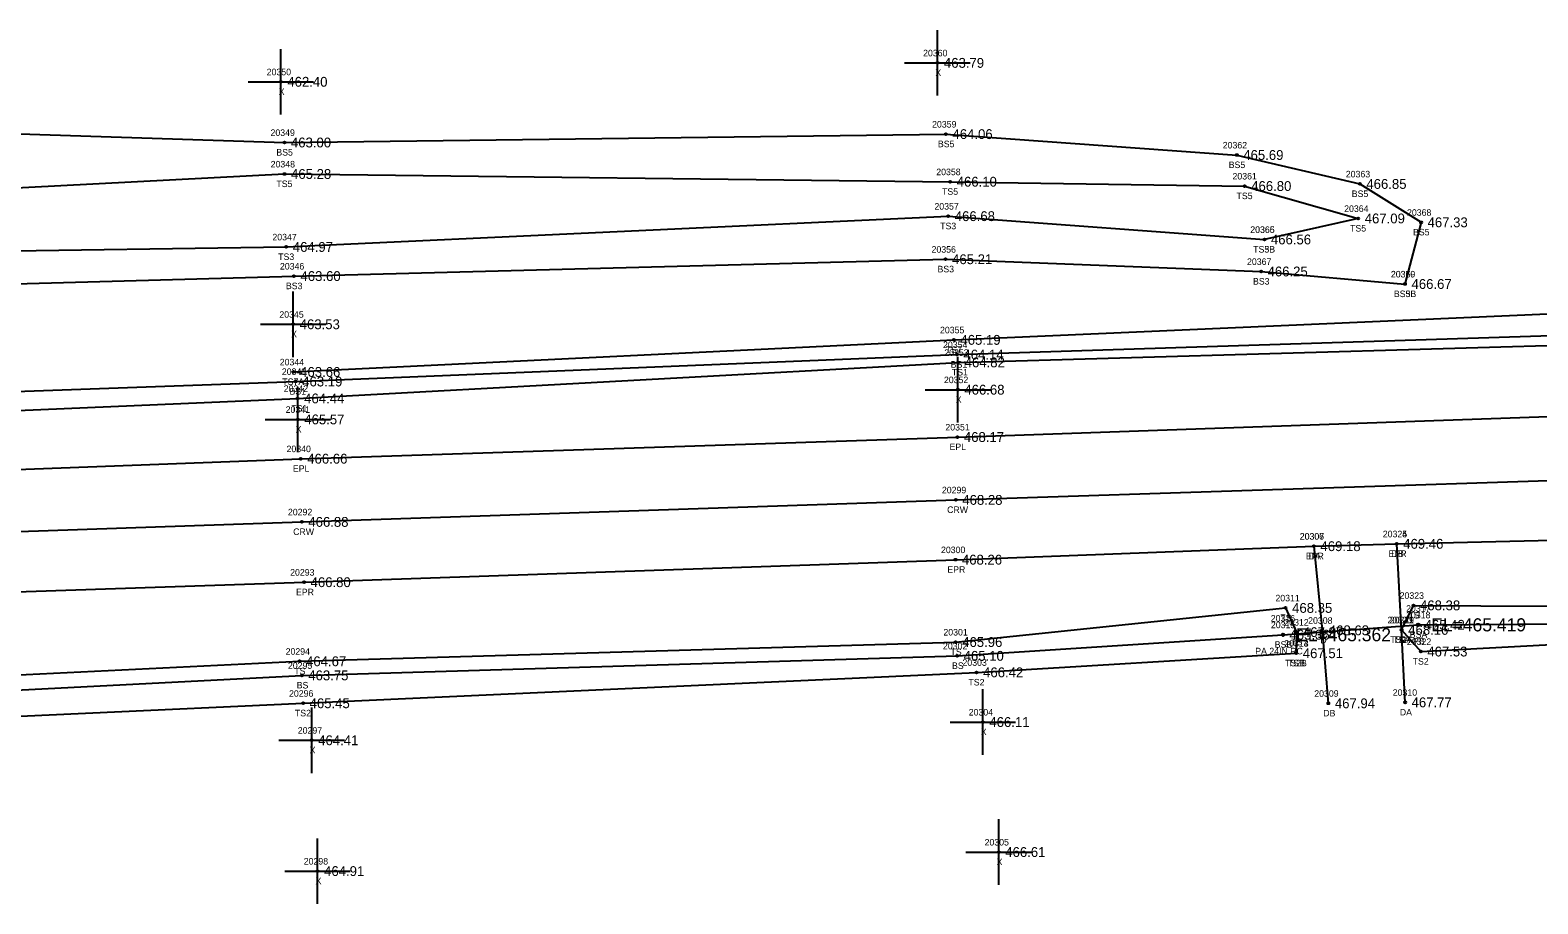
# Model space of a CAD drawing. Extents: x 1785066 to 1786589, y 770293 to 771312.
# Drawn here: x 1786037.5 to 1786267.8, y 770805.5 to 770939 of the extents above; entities that cross this region are included whole.
import ezdxf

# ---------------------------------------------------------------- set-up
doc = ezdxf.new("R2010")
doc.units = 0
for name, color, linetype in [('Default', 7, 'Continuous'), ('RD_DTM_BkLn1', 7, 'Continuous'), ('RD_DTM_BkLn2', 7, 'Continuous'), ('RD_DTM_BkLn_txCode', 7, 'Continuous'), ('RD_EX_DR_Pipe_txCode', 7, 'Continuous'), ('RD_EX_Driveway', 7, 'Continuous'), ('RD_EX_Driveway_txCode', 7, 'Continuous'), ('RD_EX_Misc', 7, 'Continuous'), ('RD_EX_Misc_txCode', 7, 'Continuous'), ('RD_EX_Road', 7, 'Continuous'), ('RD_EX_Road_txCode', 7, 'Continuous'), ('RD_EX_TX_Driveway_ELEV', 7, 'Continuous'), ('RD_EX_TX_Misc_ELEV', 7, 'Continuous'), ('RD_EX_TX_Road_ELEV', 7, 'Continuous'), ('RD_HC_Survey_ELEV', 7, 'Continuous'), ('RD_HC_Survey_txCode', 7, 'Continuous'), ('RD_SMD_Locator', 7, 'Continuous'), ('RD_TX_Pipe_ElevEX', 7, 'Continuous')]:
    doc.layers.add(name, color=color, linetype=linetype)

msp = doc.modelspace()

# ---------------------------------------------------------------- linework, layer by layer
at = {"layer": 'Default'}
msp.add_line((1786228.83, 770846.64), (1786249.47, 770848.15), dxfattribs=at)
at = {"layer": 'RD_DTM_BkLn1'}
msp.add_lwpolyline([(1785825, 770854.98), (1785879.1, 770857.22), (1785979.05, 770860.47), (1786078.95, 770863.87), (1786178.85, 770867.23), (1786278.74, 770870.52), (1786378.69, 770873.93), (1786478.55, 770877.83), (1786578.48, 770880.72)], dxfattribs=at)
at = {"layer": 'RD_DTM_BkLn2'}
for points in [[(1785924.35, 770938.04), (1785979.77, 770924.96), (1786076.29, 770921.81), (1786177.35, 770923.09), (1786221.77, 770919.9), (1786240.57, 770915.48), (1786249.92, 770909.62), (1786247.47, 770900.2)], [(1785908.96, 770920.93), (1785918.22, 770904.46), (1785926.35, 770898.09), (1785975.82, 770898.61), (1786077.75, 770901.41), (1786177.29, 770903.98), (1786225.48, 770902.11), (1786247.47, 770900.2)], [(1785930.03, 770918.87), (1785930.77, 770909.48), (1785938.68, 770905.47), (1785979.27, 770904.46), (1786076.58, 770905.86), (1786177.7, 770910.56), (1786225.99, 770907)], [(1785930.03, 770918.87), (1785938.67, 770915.93), (1785979.63, 770911.96), (1786076.31, 770917), (1786177.99, 770915.82), (1786222.98, 770915.16), (1786240.32, 770910.21), (1786225.99, 770907)], [(1786077.7, 770886.77), (1786178.56, 770891.67), (1786277.37, 770895.98), (1786358.4, 770903.56), (1786359.59, 770898.17), (1786358.22, 770894.11)], [(1785823.92, 770890.03), (1785878.49, 770883.8), (1785927.98, 770885.02), (1785976.75, 770881.71), (1786078.01, 770885.31), (1786179.02, 770889.42), (1786277.82, 770892.61), (1786356.85, 770898.28)], [(1785823.56, 770878.59), (1785827.04, 770881.87), (1785879.17, 770873.62), (1785928.77, 770880.68), (1785976.07, 770878.36), (1786078.31, 770882.72), (1786179.21, 770888.23), (1786278, 770891.06), (1786358.22, 770894.11)], [(1785823.92, 770890.03), (1785823.56, 770878.59), (1785822.86, 770870.38), (1785821.44, 770840.38), (1785828.62, 770840.78), (1785842.19, 770836.7), (1785879.25, 770839.01), (1785978.35, 770837.69), (1786078.6, 770842.58), (1786178.83, 770845.52), (1786229.23, 770850.73), (1786230.88, 770847.03), (1786230.86, 770843.81)], [(1786246.96, 770847.38), (1786248.77, 770851.12), (1786279.67, 770850.97), (1786379.11, 770855.94), (1786479.26, 770860.11), (1786579.22, 770863.72)], [(1786249.47, 770848.15), (1786280.2, 770848.37), (1786379.05, 770854.35), (1786479.51, 770858.4), (1786579.5, 770861.84)], [(1786246.96, 770847.38), (1786249.88, 770844.07), (1786279.41, 770845.63), (1786378.93, 770852.05), (1786480.11, 770854.27), (1786579.39, 770853.78)], [(1785827.67, 770829.52), (1785841.85, 770827.95), (1785844.56, 770828.57), (1785879.6, 770830.99), (1785978.6, 770835.28), (1786078.94, 770840.43), (1786179.05, 770843.41), (1786228.83, 770846.64)], [(1785823.45, 770822.61), (1785818.3, 770824.93), (1785815.32, 770825.6), (1785815.62, 770826.83), (1785818.45, 770825.65), (1785827.36, 770825.61), (1785879.44, 770828.14), (1785979.38, 770831.62), (1786079.14, 770836.17), (1786182.02, 770840.89), (1786230.86, 770843.81)]]:
    msp.add_lwpolyline(points, dxfattribs=at)
at = {"layer": 'RD_EX_Driveway'}
for points in [[(1786233.56, 770860.16), (1786234.84, 770847.31), (1786235.76, 770836.16)], [(1786247.48, 770836.31), (1786246.96, 770847.38), (1786246.2, 770860.52)]]:
    msp.add_lwpolyline(points, dxfattribs=at)
at = {"layer": 'RD_EX_Misc'}
for p, q in [((1786176.04, 770928.97), (1786176.04, 770938.97)), ((1786075.74, 770926.08), (1786075.74, 770936.08)), ((1786171.04, 770933.97), (1786181.04, 770933.97)), ((1786070.74, 770931.08), (1786080.74, 770931.08)), ((1786077.63, 770889.05), (1786077.63, 770899.05)), ((1786072.63, 770894.05), (1786082.63, 770894.05)), ((1786179.16, 770879.06), (1786179.16, 770889.06)), ((1786078.33, 770874.52), (1786078.33, 770884.52)), ((1786174.16, 770884.06), (1786184.16, 770884.06)), ((1786073.33, 770879.52), (1786083.33, 770879.52)), ((1786182.98, 770828.3), (1786182.98, 770838.3)), ((1786080.46, 770825.52), (1786080.46, 770835.52)), ((1786177.98, 770833.3), (1786187.98, 770833.3)), ((1786075.46, 770830.52), (1786085.46, 770830.52)), ((1786185.41, 770808.45), (1786185.41, 770818.45)), ((1786081.36, 770805.54), (1786081.36, 770815.54)), ((1786180.41, 770813.45), (1786190.41, 770813.45)), ((1786076.36, 770810.54), (1786086.36, 770810.54))]:
    msp.add_line(p, q, dxfattribs=at)
at = {"layer": 'RD_EX_Road'}
for points in [[(1785824.57, 770864.86), (1785879.1, 770866.73), (1785977.08, 770869.67), (1786078.78, 770873.52), (1786179.09, 770876.83), (1786278.08, 770880.28), (1786358.72, 770883.31), (1786381.38, 770883.94), (1786478.25, 770886.75), (1786578.04, 770889.63)], [(1785825.31, 770845.6), (1785879.29, 770848.18), (1785979.17, 770851.29), (1786079.29, 770854.66), (1786178.79, 770858.1), (1786233.56, 770860.16), (1786246.2, 770860.52), (1786278.61, 770861.3), (1786379.15, 770864.94), (1786479.01, 770868.57), (1786578.78, 770871.53)]]:
    msp.add_lwpolyline(points, dxfattribs=at)
at = {"layer": 'RD_SMD_Locator'}
for centre, radius in [((1786176.04, 770933.97), 0.15), ((1786075.74, 770931.08), 0.15), ((1786177.35, 770923.09), 0.15), ((1786076.29, 770921.81), 0.15), ((1786221.77, 770919.9), 0.15), ((1786076.31, 770917), 0.15), ((1786177.99, 770915.82), 0.15), ((1786222.98, 770915.16), 0.15), ((1786240.57, 770915.48), 0.15), ((1786177.7, 770910.56), 0.15), ((1786240.32, 770910.21), 0.15), ((1786249.92, 770909.62), 0.15), ((1786225.99, 770907), 0.15), ((1786225.99, 770907), 0.15), ((1786076.58, 770905.86), 0.15), ((1786177.29, 770903.98), 0.15), ((1786077.75, 770901.41), 0.15), ((1786225.48, 770902.11), 0.15), ((1786247.47, 770900.2), 0.15), ((1786247.47, 770900.2), 0.15), ((1786077.63, 770894.05), 0.15), ((1786178.56, 770891.67), 0.15), ((1786179.02, 770889.42), 0.15), ((1786077.7, 770886.77), 0.15), ((1786179.21, 770888.23), 0.15), ((1786078.01, 770885.31), 0.15), ((1786179.16, 770884.06), 0.15), ((1786078.31, 770882.72), 0.15), ((1786078.33, 770879.52), 0.15), ((1786179.09, 770876.83), 0.15), ((1786078.78, 770873.52), 0.15), ((1786178.85, 770867.23), 0.15), ((1786078.95, 770863.87), 0.15), ((1786233.56, 770860.16), 0.15), ((1786233.56, 770860.16), 0.15), ((1786246.2, 770860.52), 0.15), ((1786246.2, 770860.52), 0.15), ((1786178.79, 770858.1), 0.15), ((1786079.29, 770854.66), 0.15), ((1786229.23, 770850.73), 0.15), ((1786248.77, 770851.12), 0.15), ((1786230.88, 770847.03), 0.15), ((1786234.84, 770847.31), 0.15), ((1786246.96, 770847.38), 0.15), ((1786246.96, 770847.38), 0.15), ((1786246.96, 770847.38), 0.15), ((1786249.47, 770848.15), 0.2), ((1786249.47, 770848.15), 0.15), ((1786178.83, 770845.52), 0.15), ((1786228.83, 770846.64), 0.2), ((1786228.83, 770846.64), 0.15), ((1786078.6, 770842.58), 0.15), ((1786179.05, 770843.41), 0.15), ((1786230.86, 770843.81), 0.15), ((1786230.86, 770843.81), 0.15), ((1786249.88, 770844.07), 0.15), ((1786078.94, 770840.43), 0.15), ((1786182.02, 770840.89), 0.15), ((1786079.14, 770836.17), 0.15), ((1786235.76, 770836.16), 0.15), ((1786247.48, 770836.31), 0.15), ((1786182.98, 770833.3), 0.15), ((1786080.46, 770830.52), 0.15), ((1786185.41, 770813.45), 0.15), ((1786081.36, 770810.54), 0.15)]:
    msp.add_circle(centre, radius, dxfattribs=at)

# ---------------------------------------------------------------- texts
at = {"layer": 'RD_DTM_BkLn_txCode'}
for s, p in [('20349', (1786074.17, 770922.81)), ('20359', (1786175.23, 770924.09)), ('BS5', (1786075.06, 770919.81)), ('BS5', (1786176.12, 770921.09)), ('20362', (1786219.63, 770920.9)), ('20348', (1786074.19, 770918)), ('BS5', (1786220.54, 770917.9)), ('20358', (1786175.87, 770916.82)), ('20361', (1786221.12, 770916.16)), ('20363', (1786238.43, 770916.48)), ('TS5', (1786075.07, 770915)), ('TS5', (1786176.75, 770913.82)), ('TS5', (1786221.74, 770913.16)), ('BS5', (1786239.34, 770913.48)), ('20357', (1786175.59, 770911.56)), ('20364', (1786238.18, 770911.21)), ('20368', (1786247.78, 770910.62)), ('TS3', (1786176.46, 770908.56)), ('20347', (1786074.46, 770906.86)), ('20366', (1786223.83, 770908)), ('20365', (1786223.85, 770908)), ('TS5', (1786239.08, 770908.21)), ('BS5', (1786248.69, 770907.62)), ('TS3', (1786075.34, 770903.86)), ('20356', (1786175.15, 770904.98)), ('TS5B', (1786224.28, 770905)), ('TS3B', (1786224.28, 770905)), ('20346', (1786075.61, 770902.41)), ('BS3', (1786176.06, 770901.98)), ('20367', (1786223.34, 770903.11)), ('BS3', (1786076.52, 770899.41)), ('BS3', (1786224.25, 770900.11)), ('20370', (1786245.31, 770901.2)), ('20369', (1786245.32, 770901.2)), ('BS5B', (1786245.77, 770898.2)), ('BS3B', (1786245.77, 770898.2)), ('20355', (1786176.44, 770892.67)), ('20354', (1786176.9, 770890.42)), ('20344', (1786075.58, 770887.77)), ('20353', (1786177.09, 770889.23)), ('TS7', (1786177.31, 770889.67)), ('20343', (1786075.9, 770886.31)), ('BS1', (1786178.08, 770887.42)), ('TS1', (1786178.25, 770886.23)), ('TS7A', (1786075.97, 770884.77)), ('20342', (1786076.19, 770883.72)), ('BS1', (1786077.07, 770883.31)), ('TS1', (1786077.35, 770880.72)), ('20311', (1786227.68, 770851.73)), ('20323', (1786246.65, 770852.12)), ('TS', (1786228.43, 770848.73)), ('20320', (1786244.8, 770848.38)), ('20319', (1786245.12, 770848.38)), ('20318', (1786247.64, 770849.15)), ('TS', (1786247.98, 770849.12)), ('20301', (1786176.96, 770846.52)), ('20315', (1786226.99, 770847.64)), ('20312', (1786229.04, 770848.03)), ('BSA', (1786248.2, 770846.15)), ('20302', (1786176.89, 770844.41)), ('BSB', (1786227.57, 770844.64)), ('20313', (1786229.02, 770844.81)), ('20314', (1786229.02, 770844.81)), ('TS', (1786230.08, 770845.03)), ('TS2A', (1786245.22, 770845.38)), ('TSA', (1786245.67, 770845.38)), ('20322', (1786247.76, 770845.07)), ('20294', (1786076.48, 770843.58)), ('TS', (1786178.04, 770843.52)), ('20303', (1786179.87, 770841.89)), ('TS2B', (1786229.14, 770841.81)), ('TSB', (1786229.59, 770841.81)), ('TS2', (1786248.64, 770842.07)), ('20295', (1786076.83, 770841.43)), ('TS', (1786077.8, 770840.58)), ('BS', (1786178.27, 770841.41)), ('20296', (1786077, 770837.17)), ('BS', (1786078.17, 770838.43)), ('TS2', (1786180.78, 770838.89)), ('TS2', (1786077.9, 770834.17))]:
    msp.add_text(s, height=1, dxfattribs=at).set_placement(p)
at = {"layer": 'RD_EX_DR_Pipe_txCode'}
for s, p in [('20316', (1786226.97, 770848.64)), ('20317', (1786247.64, 770850.15)), ('PB', (1786248.69, 770845.15)), ('PA 24IN RC', (1786224.59, 770843.64))]:
    msp.add_text(s, height=1, dxfattribs=at).set_placement(p)
at = {"layer": 'RD_EX_Driveway_txCode'}
for s, p in [('20307', (1786231.41, 770861.16)), ('20324', (1786244.08, 770861.52)), ('DA', (1786232.77, 770858.16)), ('DB', (1786245.42, 770858.52)), ('20321', (1786245.12, 770848.38)), ('20308', (1786232.68, 770848.31)), ('D', (1786234.54, 770845.31)), ('D', (1786246.65, 770845.38)), ('20309', (1786233.61, 770837.16)), ('20310', (1786245.6, 770837.31)), ('DB', (1786234.98, 770834.16)), ('DA', (1786246.68, 770834.31))]:
    msp.add_text(s, height=1, dxfattribs=at).set_placement(p)
at = {"layer": 'RD_EX_Misc_txCode'}
for s, p in [('20360', (1786173.86, 770934.97)), ('20350', (1786073.59, 770932.08)), ('X', (1786175.73, 770931.97)), ('X', (1786075.43, 770929.08)), ('20345', (1786075.52, 770895.05)), ('X', (1786077.32, 770892.05)), ('20352', (1786177.04, 770885.06)), ('X', (1786178.84, 770882.06)), ('20341', (1786076.49, 770880.52)), ('X', (1786078.01, 770877.52)), ('20304', (1786180.83, 770834.3)), ('20297', (1786078.34, 770831.52)), ('X', (1786182.67, 770831.3)), ('X', (1786080.14, 770828.52)), ('20305', (1786183.25, 770814.45)), ('20298', (1786079.25, 770811.54)), ('X', (1786185.09, 770811.45)), ('X', (1786081.05, 770808.54))]:
    msp.add_text(s, height=1, dxfattribs=at).set_placement(p)
at = {"layer": 'RD_EX_Road_txCode'}
for s, p in [('20351', (1786177.26, 770877.83)), ('20340', (1786076.62, 770874.52)), ('EPL', (1786177.89, 770874.83)), ('EPL', (1786077.58, 770871.52)), ('20306', (1786231.38, 770861.16)), ('20325', (1786244.08, 770861.52)), ('20300', (1786176.59, 770859.1)), ('EPR', (1786232.33, 770858.16)), ('EPR', (1786244.97, 770858.52)), ('20293', (1786077.17, 770855.66)), ('EPR', (1786177.56, 770856.1)), ('EPR', (1786078.06, 770852.66))]:
    msp.add_text(s, height=1, dxfattribs=at).set_placement(p)
at = {"layer": 'RD_EX_TX_Driveway_ELEV'}
for s, p in [('469.18', (1786234.56, 770859.41)), ('469.46', (1786247.2, 770859.77)), ('468.63', (1786235.84, 770846.56)), ('468.16', (1786247.96, 770846.63)), ('467.94', (1786236.76, 770835.41)), ('467.77', (1786248.48, 770835.56))]:
    msp.add_text(s, height=1.5, dxfattribs=at).set_placement(p)
at = {"layer": 'RD_EX_TX_Misc_ELEV'}
for s, p in [('463.79', (1786177.04, 770933.22)), ('462.40', (1786076.74, 770930.33)), ('464.06', (1786178.35, 770922.34)), ('463.00', (1786077.29, 770921.06)), ('465.69', (1786222.77, 770919.15)), ('465.28', (1786077.31, 770916.25)), ('466.10', (1786178.99, 770915.07)), ('466.85', (1786241.57, 770914.73)), ('466.80', (1786223.98, 770914.41)), ('466.68', (1786178.7, 770909.81)), ('467.09', (1786241.32, 770909.46)), ('467.33', (1786250.92, 770908.87)), ('466.56', (1786226.99, 770906.25)), ('466.56', (1786226.99, 770906.25)), ('464.97', (1786077.58, 770905.11)), ('465.21', (1786178.29, 770903.23)), ('466.25', (1786226.48, 770901.36)), ('463.60', (1786078.75, 770900.66)), ('466.67', (1786248.47, 770899.45)), ('466.67', (1786248.47, 770899.45)), ('463.53', (1786078.63, 770893.3)), ('465.19', (1786179.56, 770890.92)), ('464.14', (1786180.02, 770888.67)), ('464.82', (1786180.21, 770887.48)), ('463.66', (1786078.7, 770886.02)), ('463.19', (1786079.01, 770884.56)), ('466.68', (1786180.16, 770883.31)), ('464.44', (1786079.31, 770881.97)), ('465.57', (1786079.33, 770878.77)), ('468.38', (1786249.77, 770850.37)), ('468.35', (1786230.23, 770849.98)), ('465.36', (1786229.83, 770845.89)), ('467.97', (1786231.88, 770846.28)), ('468.16', (1786247.96, 770846.63)), ('468.16', (1786247.96, 770846.63)), ('465.42', (1786250.47, 770847.4)), ('465.96', (1786179.83, 770844.77)), ('467.53', (1786250.88, 770843.32)), ('464.67', (1786079.6, 770841.83)), ('465.10', (1786180.05, 770842.66)), ('467.51', (1786231.86, 770843.06)), ('467.51', (1786231.86, 770843.06)), ('463.75', (1786079.94, 770839.68)), ('466.42', (1786183.02, 770840.14)), ('465.45', (1786080.14, 770835.42)), ('466.11', (1786183.98, 770832.55)), ('464.41', (1786081.46, 770829.77)), ('466.61', (1786186.41, 770812.7)), ('464.91', (1786082.36, 770809.79))]:
    msp.add_text(s, height=1.5, dxfattribs=at).set_placement(p)
at = {"layer": 'RD_EX_TX_Road_ELEV'}
for s, p in [('468.17', (1786180.09, 770876.08)), ('466.66', (1786079.78, 770872.77)), ('469.18', (1786234.56, 770859.41)), ('469.46', (1786247.2, 770859.77)), ('468.26', (1786179.79, 770857.35)), ('466.80', (1786080.29, 770853.91))]:
    msp.add_text(s, height=1.5, dxfattribs=at).set_placement(p)
at = {"layer": 'RD_HC_Survey_ELEV'}
for s, p in [('468.28', (1786179.85, 770866.48)), ('466.88', (1786079.95, 770863.12))]:
    msp.add_text(s, height=1.5, dxfattribs=at).set_placement(p)
at = {"layer": 'RD_HC_Survey_txCode'}
for s, p in [('20299', (1786176.73, 770868.23)), ('20292', (1786076.83, 770864.87)), ('CRW', (1786177.53, 770865.23)), ('CRW', (1786077.63, 770861.87))]:
    msp.add_text(s, height=1, dxfattribs=at).set_placement(p)
at = {"layer": 'RD_TX_Pipe_ElevEX'}
for s, p in [('EL=465.362', (1786230.83, 770845.64)), ('EL=465.419', (1786251.47, 770847.15))]:
    msp.add_text(s, height=2, dxfattribs=at).set_placement(p)

doc.saveas('drawing.dxf')
